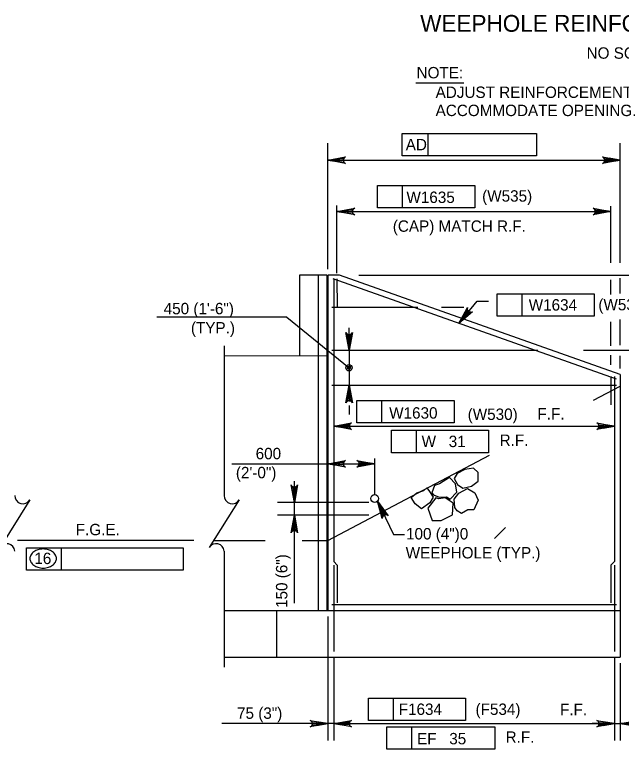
# Model space of a CAD drawing. Extents: x 634540 to 640306, y 296059 to 300275.
# Drawn here: x 639583.4 to 639742.9, y 297941.5 to 298134.8 of the extents above; entities that cross this region are included whole.
import ezdxf

# ---------------------------------------------------------------- set-up
doc = ezdxf.new("R2010")
doc.units = 0
for name, color, linetype in [('10', 7, 'Continuous'), ('3', 7, 'Continuous'), ('4', 7, 'Continuous'), ('5', 7, 'Continuous'), ('6', 7, 'Continuous')]:
    doc.layers.add(name, color=color, linetype=linetype)

# ---------------------------------------------------------------- blocks, each defined once
blk = doc.blocks.new('ROCK')
at = {"layer": '4'}
for points in [[(2.36725, 1.088), (2.2065, 0.82625), (2.378625, 0.506625), (2.66975, 0.3095), (3.128875, 0.403375), (3.48475, 0.6775), (3.4915, 1.123375), (3.25625, 1.36725), (2.783625, 1.308375)], [(1.10175, -0.02725), (1.4015, -0.159125), (1.78825, -0.148875), (1.980875, -0.266), (2.343375, 0.09475), (2.27875, 0.5505), (1.969375, 0.883), (1.4225, 0.553625), (1.152875, 0.479), (1.0105, 0.082)], [(0.74675, 0.359875), (0.882, 0.16), (1.072875, -0.144), (0.892, -0.457375), (0.448125, -0.758625), (0.1, -0.49325), (-0.095, -0.146375), (0.202875, 0.1025), (0.579125, 0.219875)], [(2.231375, -0.71725), (2.2025, -0.266375), (2.45475, 0.037125), (2.9085, 0.28875), (3.2995, 0.047625), (3.46875, -0.344), (3.231625, -0.855), (2.92, -0.860375), (2.5765, -1.054625), (2.340375, -0.904375)], [(1.2085, -0.192875), (0.778375, -0.737625), (1.008375, -1.391375), (1.48725, -1.396875), (2.09825, -1.106625), (2.133375, -0.486375), (1.723125, -0.203375), (1.37425, -0.239875)]]:
    blk.add_lwpolyline(points, close=True, dxfattribs=at)

msp = doc.modelspace()

# ---------------------------------------------------------------- linework, layer by layer
at = {"layer": '10'}
for p, q in [((639665.48, 298066.32), (639658.27, 298066.32)), ((639658.27, 298066.32), (639658.27, 298045.05)), ((639663.14, 298066.32), (639663.14, 297978.04)), ((639665.48, 298066.32), (639665.48, 297978.04)), ((639665.73, 298066.32), (639665.73, 297978.04)), ((639668.81, 298066.32), (639665.73, 298066.32)), ((639742.63, 298040.17), (639668.81, 298066.32)), ((639638.46, 298045.15), (639665.48, 298045.03)), ((639742.63, 298040.17), (639742.63, 297965.74)), ((639735.55, 298033.36), (639742.63, 298037.1)), ((639665.73, 297996.5), (639708.27, 298018.96)), ((639635.71, 297996.5), (639649.26, 297996.5)), ((639658.98, 297996.5), (639665.73, 297996.5)), ((639638.46, 297978.04), (639742.63, 297978.04)), ((639652.26, 297978.04), (639652.26, 297965.74)), ((639638.46, 297965.74), (639742.63, 297965.74))]:
    msp.add_line(p, q, dxfattribs=at)
at = {"layer": '3'}
for p, q in [((639654.93, 298055.27), (639620.73, 298055.27)), ((639638.46, 298047.73), (639638.46, 298008.26)), ((639587.35, 298007.19), (639579.45, 297994.63)), ((639642.44, 298007.19), (639634.54, 297994.63)), ((639638.46, 297993.69), (639638.46, 297963.11))]:
    msp.add_line(p, q, dxfattribs=at)
for radius in [0.833, 0.417]:
    msp.add_circle((639671.3, 298041.92), radius, dxfattribs=at)
for centre, start, end in [((639585.51, 298008.26), 180, 330), ((639640.59, 298008.26), 180, 330), ((639581.25, 297993.49), 5.3286, 147.8672), ((639636.34, 297993.49), 5.3286, 147.8672)]:
    msp.add_arc(centre, 2.13, start, end, dxfattribs=at)
at = {"layer": '4'}
for p, q in [((639688.88, 298116.91), (639701.5, 298116.91)), ((639685.26, 298103.58), (639720.56, 298103.58)), ((639685.26, 298097.67), (639685.26, 298103.58)), ((639692.1, 298097.67), (639692.1, 298103.58)), ((639720.56, 298103.58), (639720.56, 298097.67)), ((639665.73, 298067.86), (639665.73, 298101.01)), ((639742.63, 298069.56), (639742.63, 298101.01)), ((639668.69, 298096.58), (639739.68, 298096.58)), ((639720.56, 298097.67), (639685.26, 298097.67)), ((639678.8, 298089.89), (639704.34, 298089.89)), ((639678.8, 298083.98), (639678.8, 298089.89)), ((639685.39, 298083.98), (639685.39, 298089.89)), ((639704.34, 298089.89), (639704.34, 298083.98)), ((639668.12, 298066.83), (639668.12, 298084.63)), ((639740.11, 298069.56), (639740.11, 298084.49)), ((639668.12, 298083.05), (639740.11, 298083.05)), ((639704.34, 298083.98), (639678.8, 298083.98)), ((639673.87, 298066.32), (639871.21, 298066.32)), ((639740.11, 298061.23), (639740.11, 298065.09)), ((639742.63, 298061.43), (639742.63, 298065.49)), ((639710.24, 298061.39), (639735.78, 298061.39)), ((639710.24, 298055.48), (639710.24, 298061.39)), ((639716.83, 298055.48), (639716.83, 298061.39)), ((639735.78, 298061.39), (639735.78, 298055.48)), ((639700.14, 298053.59), (639705.02, 298059.49)), ((639705.02, 298059.49), (639707.97, 298059.49)), ((639695.58, 298057.91), (639701.51, 298057.91)), ((639735.78, 298055.48), (639710.24, 298055.48)), ((639654.93, 298055.27), (639671.3, 298041.92)), ((639740.11, 298047.68), (639740.11, 298054.05)), ((639742.63, 298047.88), (639742.63, 298054.62)), ((639671.3, 298049.49), (639671.3, 298052.44)), ((639671.3, 298046.53), (639671.3, 298037.31)), ((639732.91, 298046.53), (639746.89, 298046.53)), ((639740.11, 298042.72), (639740.11, 298045.2)), ((639742.63, 298041.71), (639742.63, 298045.06)), ((639673.37, 298033.3), (639698.91, 298033.3)), ((639673.37, 298027.4), (639673.37, 298033.3)), ((639679.96, 298027.4), (639679.96, 298033.3)), ((639698.91, 298033.3), (639698.91, 298027.4)), ((639671.3, 298031.99), (639671.3, 298029.6)), ((639667.27, 298026.54), (639741.09, 298026.54)), ((639698.91, 298027.4), (639673.37, 298027.4)), ((639682.43, 298025.47), (639707.97, 298025.47)), ((639682.43, 298019.56), (639682.43, 298025.47)), ((639689.03, 298019.56), (639689.03, 298025.47)), ((639707.97, 298025.47), (639707.97, 298019.56)), ((639707.97, 298019.56), (639682.43, 298019.56)), ((639678.04, 298008.52), (639678.04, 298018.06)), ((639640.5, 298016.68), (639678.04, 298016.68)), ((639656.91, 297979.96), (639656.91, 298012.1)), ((639676.5, 298006.47), (639652.48, 298006.47)), ((639678.81, 298006.82), (639682.95, 297998.03)), ((639676.5, 298003.12), (639652.48, 298003.12)), ((639709.56, 297996.98), (639712.44, 297999.85)), ((639682.95, 297998.03), (639685.9, 297998.03)), ((639630.45, 297996.5), (639584.13, 297996.5)), ((639586.49, 297994.56), (639627.7, 297994.56)), ((639586.49, 297988.66), (639586.49, 297994.56)), ((639595.66, 297988.66), (639595.66, 297994.56)), ((639627.7, 297994.56), (639627.7, 297988.66)), ((639627.7, 297988.66), (639586.49, 297988.66)), ((639665.73, 297976.5), (639665.73, 297943.83)), ((639667.27, 297965.74), (639667.27, 297943.83)), ((639741.09, 297965.74), (639741.09, 297943.83)), ((639742.63, 297964.2), (639742.63, 297943.83)), ((639676.41, 297954.98), (639701.94, 297954.98)), ((639676.41, 297949.07), (639676.41, 297954.98)), ((639683, 297949.07), (639683, 297954.98)), ((639701.94, 297954.98), (639701.94, 297949.07)), ((639701.94, 297949.07), (639676.41, 297949.07)), ((639659.83, 297948.26), (639637.86, 297948.26)), ((639662.78, 297948.26), (639659.83, 297948.26)), ((639667.27, 297948.26), (639665.73, 297948.26)), ((639670.22, 297948.26), (639738.14, 297948.26)), ((639670.22, 297948.26), (639673.18, 297948.26)), ((639681.22, 297947.42), (639709.64, 297947.42)), ((639681.22, 297941.51), (639681.22, 297947.42)), ((639687.81, 297941.51), (639687.81, 297947.42)), ((639709.64, 297947.42), (639709.64, 297941.51)), ((639738.14, 297948.26), (639735.19, 297948.26)), ((639741.09, 297948.26), (639742.63, 297948.26)), ((639709.64, 297941.51), (639681.22, 297941.51))]:
    msp.add_line(p, q, dxfattribs=at)
for points in [[(639665.73, 298096.58), (639670.4, 298097.46), (639670.04, 298097.21), (639669.85, 298096.9), (639669.8, 298096.58), (639669.85, 298096.27), (639670.04, 298095.96), (639670.4, 298095.71), (639665.73, 298096.58), (639670.04, 298095.96), (639669.85, 298096.27), (639665.73, 298096.58), (639669.8, 298096.58), (639669.85, 298096.9), (639665.73, 298096.58), (639670.04, 298097.21)], [(639742.63, 298096.58), (639737.97, 298095.71), (639738.33, 298095.96), (639738.51, 298096.27), (639738.57, 298096.58), (639738.51, 298096.9), (639738.33, 298097.21), (639737.97, 298097.46), (639742.63, 298096.58), (639738.33, 298097.21), (639738.51, 298096.9), (639742.63, 298096.58), (639738.57, 298096.58), (639738.51, 298096.27), (639742.63, 298096.58), (639738.33, 298095.96)], [(639668.12, 298083.05), (639672.78, 298083.93), (639672.42, 298083.68), (639672.24, 298083.37), (639672.18, 298083.05), (639672.24, 298082.74), (639672.42, 298082.43), (639672.78, 298082.18), (639668.12, 298083.05), (639672.42, 298082.43), (639672.24, 298082.74), (639668.12, 298083.05), (639672.18, 298083.05), (639672.24, 298083.37), (639668.12, 298083.05), (639672.42, 298083.68)], [(639740.11, 298083.05), (639735.45, 298082.18), (639735.8, 298082.43), (639735.99, 298082.74), (639736.04, 298083.05), (639735.99, 298083.37), (639735.8, 298083.68), (639735.45, 298083.93), (639740.11, 298083.05), (639735.8, 298083.68), (639735.99, 298083.37), (639740.11, 298083.05), (639736.04, 298083.05), (639735.99, 298082.74), (639740.11, 298083.05), (639735.8, 298082.43)], [(639700.14, 298053.59), (639702.44, 298057.74), (639702.4, 298057.31), (639702.52, 298056.96), (639702.73, 298056.72), (639703, 298056.56), (639703.36, 298056.51), (639703.78, 298056.63), (639700.14, 298053.59), (639703.36, 298056.51), (639703, 298056.56), (639700.14, 298053.59), (639702.73, 298056.72), (639702.52, 298056.96), (639700.14, 298053.59), (639702.4, 298057.31)], [(639671.3, 298046.53), (639670.42, 298051.2), (639670.67, 298050.84), (639670.98, 298050.65), (639671.3, 298050.6), (639671.61, 298050.65), (639671.92, 298050.84), (639672.17, 298051.2), (639671.3, 298046.53), (639671.92, 298050.84), (639671.61, 298050.65), (639671.3, 298046.53), (639671.3, 298050.6), (639670.98, 298050.65), (639671.3, 298046.53), (639670.67, 298050.84)], [(639671.3, 298037.31), (639672.17, 298032.65), (639671.92, 298033), (639671.61, 298033.19), (639671.3, 298033.24), (639670.98, 298033.19), (639670.67, 298033), (639670.42, 298032.65), (639671.3, 298037.31), (639670.67, 298033), (639670.98, 298033.19), (639671.3, 298037.31), (639671.3, 298033.24), (639671.61, 298033.19), (639671.3, 298037.31), (639671.92, 298033)], [(639667.27, 298026.54), (639671.93, 298027.41), (639671.57, 298027.16), (639671.39, 298026.85), (639671.33, 298026.54), (639671.39, 298026.23), (639671.57, 298025.91), (639671.93, 298025.67), (639667.27, 298026.54), (639671.57, 298025.91), (639671.39, 298026.23), (639667.27, 298026.54), (639671.33, 298026.54), (639671.39, 298026.85), (639667.27, 298026.54), (639671.57, 298027.16)], [(639741.09, 298026.54), (639736.43, 298025.67), (639736.79, 298025.91), (639736.98, 298026.23), (639737.03, 298026.54), (639736.98, 298026.85), (639736.79, 298027.16), (639736.43, 298027.41), (639741.09, 298026.54), (639736.79, 298027.16), (639736.98, 298026.85), (639741.09, 298026.54), (639737.03, 298026.54), (639736.98, 298026.23), (639741.09, 298026.54), (639736.79, 298025.91)], [(639665.73, 298016.65), (639670.4, 298017.52), (639670.04, 298017.27), (639669.85, 298016.96), (639669.8, 298016.65), (639669.85, 298016.34), (639670.04, 298016.02), (639670.4, 298015.77), (639665.73, 298016.65), (639670.04, 298016.02), (639669.85, 298016.34), (639665.73, 298016.65), (639669.8, 298016.65), (639669.85, 298016.96), (639665.73, 298016.65), (639670.04, 298017.27)], [(639678.04, 298016.65), (639673.38, 298015.77), (639673.73, 298016.02), (639673.92, 298016.34), (639673.97, 298016.65), (639673.92, 298016.96), (639673.73, 298017.27), (639673.38, 298017.52), (639678.04, 298016.65), (639673.73, 298017.27), (639673.92, 298016.96), (639678.04, 298016.65), (639673.97, 298016.65), (639673.92, 298016.34), (639678.04, 298016.65), (639673.73, 298016.02)], [(639656.91, 298006.47), (639656.04, 298011.13), (639656.29, 298010.77), (639656.6, 298010.59), (639656.91, 298010.53), (639657.22, 298010.59), (639657.54, 298010.77), (639657.78, 298011.13), (639656.91, 298006.47), (639657.54, 298010.77), (639657.22, 298010.59), (639656.91, 298006.47), (639656.91, 298010.53), (639656.6, 298010.59), (639656.91, 298006.47), (639656.29, 298010.77)], [(639678.81, 298006.82), (639681.59, 298002.97), (639681.21, 298003.19), (639680.85, 298003.23), (639680.54, 298003.14), (639680.28, 298002.96), (639680.07, 298002.66), (639680, 298002.23), (639678.81, 298006.82), (639680.07, 298002.66), (639680.28, 298002.96), (639678.81, 298006.82), (639680.54, 298003.14), (639680.85, 298003.23), (639678.81, 298006.82), (639681.21, 298003.19)], [(639656.91, 298003.12), (639657.78, 297998.46), (639657.54, 297998.81), (639657.22, 297999), (639656.91, 297999.05), (639656.6, 297999), (639656.29, 297998.81), (639656.04, 297998.46), (639656.91, 298003.12), (639656.29, 297998.81), (639656.6, 297999), (639656.91, 298003.12), (639656.91, 297999.05), (639657.22, 297999), (639656.91, 298003.12), (639657.54, 297998.81)], [(639665.73, 297948.26), (639661.07, 297947.39), (639661.43, 297947.64), (639661.62, 297947.95), (639661.67, 297948.26), (639661.62, 297948.57), (639661.43, 297948.89), (639661.07, 297949.13), (639665.73, 297948.26), (639661.43, 297948.89), (639661.62, 297948.57), (639665.73, 297948.26), (639661.67, 297948.26), (639661.62, 297947.95), (639665.73, 297948.26), (639661.43, 297947.64)], [(639667.27, 297948.26), (639671.93, 297949.13), (639671.57, 297948.89), (639671.39, 297948.57), (639671.33, 297948.26), (639671.39, 297947.95), (639671.57, 297947.64), (639671.93, 297947.39), (639667.27, 297948.26), (639671.57, 297947.64), (639671.39, 297947.95), (639667.27, 297948.26), (639671.33, 297948.26), (639671.39, 297948.57), (639667.27, 297948.26), (639671.57, 297948.89)], [(639741.09, 297948.26), (639736.43, 297947.39), (639736.79, 297947.64), (639736.98, 297947.95), (639737.03, 297948.26), (639736.98, 297948.57), (639736.79, 297948.89), (639736.43, 297949.13), (639741.09, 297948.26), (639736.79, 297948.89), (639736.98, 297948.57), (639741.09, 297948.26), (639737.03, 297948.26), (639736.98, 297947.95), (639741.09, 297948.26), (639736.79, 297947.64)], [(639742.63, 297948.26), (639747.29, 297949.13), (639746.93, 297948.89), (639746.75, 297948.57), (639746.69, 297948.26), (639746.75, 297947.95), (639746.93, 297947.64), (639747.29, 297947.39), (639742.63, 297948.26), (639746.93, 297947.64), (639746.75, 297947.95), (639742.63, 297948.26), (639746.69, 297948.26), (639746.75, 297948.57), (639742.63, 297948.26), (639746.93, 297948.89)]]:
    msp.add_lwpolyline(points, dxfattribs=at)
for points in [[(639668.69, 298097.08), (639668.69, 298096.09), (639665.73, 298096.58)], [(639739.68, 298097.08), (639739.68, 298096.09), (639742.63, 298096.58)], [(639702.4, 298055.55), (639701.64, 298056.18), (639700.14, 298053.59)], [(639670.8, 298049.49), (639671.79, 298049.49), (639671.3, 298046.53)], [(639670.8, 298034.35), (639671.79, 298034.35), (639671.3, 298037.31)], [(639670.22, 298027.03), (639670.22, 298026.05), (639667.27, 298026.54)], [(639738.14, 298027.03), (639738.14, 298026.05), (639741.09, 298026.54)], [(639668.69, 298017.14), (639668.69, 298016.15), (639665.73, 298016.65)], [(639656.42, 298009.42), (639657.4, 298009.42), (639656.91, 298006.47)], [(639679.62, 298003.94), (639680.51, 298004.36), (639678.81, 298006.82)], [(639656.42, 298000.16), (639657.4, 298000.16), (639656.91, 298003.12)], [(639662.78, 297948.75), (639662.78, 297947.77), (639665.73, 297948.26)], [(639670.22, 297948.75), (639670.22, 297947.77), (639667.27, 297948.26)], [(639738.14, 297948.75), (639738.14, 297947.77), (639741.09, 297948.26)], [(639745.59, 297948.75), (639745.59, 297947.77), (639742.63, 297948.26)]]:
    msp.add_lwpolyline(points, close=True, dxfattribs=at)
msp.add_circle((639678.04, 298007.5), 1.03, dxfattribs=at)
for centre, radius, start, end in [((639590.52, 297990.52), 3.66, 106.5358, 125.6316), ((639590.87, 297989.36), 4.87, 90, 106.5358), ((639590.87, 297989.36), 4.87, 73.4642, 90), ((639591.21, 297990.52), 3.66, 54.3684, 73.4642), ((639589.19, 297991.72), 1.83, 149.9767, 180), ((639589.19, 297991.72), 1.83, 180, 210.0233), ((639590, 297991.25), 2.76, 125.6316, 149.9767), ((639591.74, 297991.25), 2.76, 30.0233, 54.3684), ((639592.54, 297991.72), 1.83, 0, 30.0233), ((639592.54, 297991.72), 1.83, 329.9767, 0), ((639590, 297992.18), 2.76, 210.0233, 234.3684), ((639590.52, 297992.92), 3.66, 234.3684, 253.4642), ((639591.21, 297992.92), 3.66, 286.5358, 305.6316), ((639591.74, 297992.18), 2.76, 305.6316, 329.9767), ((639590.87, 297994.08), 4.87, 253.4642, 270), ((639590.87, 297994.08), 4.87, 270, 286.5358)]:
    msp.add_arc(centre, radius, start, end, dxfattribs=at)
at = {"layer": '5'}
for p, q in [((639668.12, 298065.29), (639668.13, 298057.85)), ((639740.1, 298039.63), (639740.11, 298032.18))]:
    msp.add_line(p, q, dxfattribs=at)
at = {"layer": '6'}
for p, q in [((639741.61, 298038.91), (639667.1, 298065.29)), ((639667.27, 298065.29), (639667.27, 297990.91)), ((639666.76, 298057.91), (639689.35, 298057.91)), ((639666.76, 298046.53), (639720.96, 298046.53)), ((639741.09, 298039.63), (639741.09, 297990.91)), ((639666.76, 298037.31), (639741.61, 298037.31)), ((639667.27, 297990.91), (639668.21, 297989.98)), ((639667.27, 297989.98), (639667.27, 297967.27)), ((639668.21, 297989.98), (639668.21, 297980.04)), ((639741.09, 297990.91), (639740.16, 297989.98)), ((639740.16, 297989.98), (639740.16, 297980.04)), ((639741.09, 297989.98), (639741.09, 297967.27)), ((639666.76, 297979.58), (639741.61, 297979.58))]:
    msp.add_line(p, q, dxfattribs=at)

# ---------------------------------------------------------------- block references
at = {"layer": '4', "xscale": 4.921475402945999, "yscale": 4.921475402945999, "rotation": 0.8865726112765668}
msp.add_blockref('ROCK', (639688.12, 298008.52), dxfattribs=at)

# ---------------------------------------------------------------- texts
at = {"layer": '3'}
for s, height, p in [('450 (1\'-6")', 3.0001, (639622.55, 298056)), ('(TYP.)', 3, (639629.71, 298050.94)), ('100 (4")0', 3, (639686.28, 297996.74))]:
    msp.add_text(s, height=height, dxfattribs=at).set_placement(p)
at = {"layer": '4'}
for s, height, p in [('WEEPHOLE REINFORCEMENT DETAIL', 4.4294, (639690, 298130.34)), ('NO SCALE', 3, (639733.76, 298123.25)), ('NOTE:', 3, (639689.05, 298118.08)), ('ADJUST REINFORCEMENT AS NECESSARY TO', 3.0001, (639694.06, 298112.93)), ('ACCOMMODATE OPENING.', 3.0001, (639694.06, 298108.15)), ('AD', 3, (639686.2, 298099.15)), ('W1635', 3, (639686.39, 298085.29)), ('(W535)', 3, (639706.3, 298085.64)), ('(CAP) MATCH R.F.', 3.0001, (639682.8, 298077.7)), ('W1634', 3, (639718.54, 298056.97)), ('(W534)', 3, (639736.86, 298057.04)), ('W1630', 3, (639681.85, 298028.53)), ('(W530)', 3, (639702.49, 298028.19)), ('F.F.', 3, (639720.84, 298028.3)), ('W   31', 3, (639690.38, 298021.04)), ('R.F.', 3, (639710.89, 298021.35)), ('600', 3, (639646.74, 298017.84)), ('(2\'-0")', 3, (639641.53, 298012.84)), ('F.G.E.', 3, (639599.43, 297997.84)), ('WEEPHOLE (TYP.)', 3.0001, (639686.19, 297991.74)), ('16', 3, (639588.54, 297990.26)), ('F1634', 3, (639684.36, 297950.56)), ('(F534)', 3, (639704.56, 297950.56)), ('F.F.', 3, (639726.77, 297950.49)), ('75 (3")', 3, (639641.84, 297949.53)), ('EF   35', 3, (639689.18, 297942.82)), ('R.F.', 3, (639712.46, 297943.23))]:
    msp.add_text(s, height=height, dxfattribs=at).set_placement(p)
msp.add_text('150 (6")', height=3, rotation=90, dxfattribs=at).set_placement((639655.08, 297978.71))

doc.saveas('drawing.dxf')
